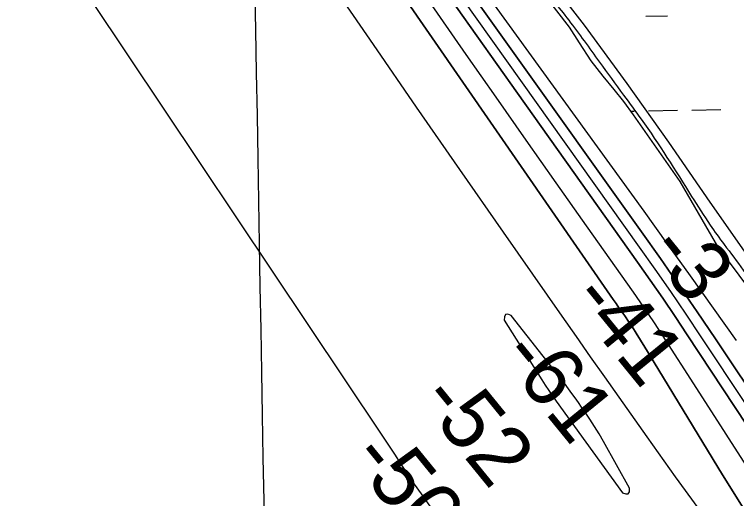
# Model space of a CAD drawing. Extents: x 3892998 to 3931244, y 278583 to 304547.
# Drawn here: x 3912822 to 3913620, y 290539 to 291075 of the extents above; entities that cross this region are included whole.
import ezdxf

# ---------------------------------------------------------------- set-up
doc = ezdxf.new("R2010")
doc.units = 0
for name, color, linetype in [('V-GRID-MAJR', 7, 'Continuous'), ('V-RIVR-EDGE', 7, 'Continuous'), ('V-RIVR-RANG', 7, 'Continuous'), ('V-RRAP-FSHR', 7, 'Continuous'), ('V-TOPO-DPTH', 7, 'Continuous'), ('V-TOPO-MAJR', 7, 'Continuous'), ('V-TOPO-MINR', 7, 'Continuous'), ('V-WETL-SWMP', 7, 'Continuous')]:
    doc.layers.add(name, color=color, linetype=linetype)

msp = doc.modelspace()

# ---------------------------------------------------------------- linework, layer by layer
at = {"layer": 'V-GRID-MAJR'}
for points in [[(3913205.694, 284291.167), (3913100.856, 290347.625), (3912995.9590000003, 296407.553), (3912891.061, 302467.47500000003), (3912891.001, 302470.95)], [(3897162.872, 290075.216), (3902475.546, 290165.246), (3907788.208, 290256.049), (3913100.856, 290347.625), (3918413.491, 290439.973), (3923726.113, 290533.094), (3929038.721, 290626.988)]]:
    msp.add_spline(points, degree=3, dxfattribs=at)
at = {"layer": 'V-RIVR-EDGE'}
msp.add_spline([(3912905.462429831, 291820.09187449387), (3912916.1993131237, 291798.1348694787), (3912921.3932742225, 291786.9827471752), (3912931.4339568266, 291765.0274636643), (3912935.9162236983, 291747.61125666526), (3912940.4122626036, 291735.7646551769), (3912954.9722244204, 291711.36147947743), (3912961.5198530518, 291684.5413986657), (3912964.258175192, 291665.73709404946), (3912967.0128516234, 291653.54669597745), (3912976.0161192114, 291634.37879747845), (3912985.7104229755, 291613.1205754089), (3912986.385104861, 291604.416345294), (3912990.545093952, 291597.4440093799), (3912997.1486714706, 291593.25045095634), (3913007.576188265, 291586.9588221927), (3913014.1746012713, 291580.67666170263), (3913019.3633978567, 291567.43593733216), (3913026.994061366, 291556.2777897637), (3913048.1808410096, 291537.07976494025), (3913061.368198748, 291520.68634017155), (3913079.061924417, 291496.62351804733), (3913103.011127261, 291468.3679982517), (3913127.304126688, 291438.37111598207), (3913184.9441775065, 291379.7473732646), (3913206.1163243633, 291354.63164258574), (3913225.1955653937, 291327.780574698), (3913253.290124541, 291286.6350131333), (3913265.0962706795, 291274.77033585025), (3913279.3373977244, 291262.20343261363), (3913304.672976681, 291231.5077673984), (3913329.3132157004, 291201.16192403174), (3913355.687931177, 291168.3750744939), (3913376.51197769, 291143.26020456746), (3913400.8006733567, 291111.5228205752), (3913434.460534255, 291068.62298525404), (3913468.459887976, 291022.24128573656), (3913495.173235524, 290985.624471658), (3913514.60143765, 290959.12064336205), (3913570.4347088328, 290873.69747788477), (3913590.894300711, 290841.9695621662), (3913606.505449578, 290820.3486069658), (3913627.3217493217, 290792.10083393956), (3913641.190674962, 290769.7879818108), (3913669.62730919, 290726.20485708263), (3913686.621391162, 290700.7513550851), (3913705.714404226, 290679.46989270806), (3913722.034665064, 290663.06872116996), (3913741.1182098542, 290637.958155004), (3913763.668125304, 290606.9212754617), (3913781.0301049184, 290589.47322063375)], degree=3, dxfattribs=at)
at = {"layer": 'V-RRAP-FSHR'}
msp.add_lwpolyline([(3912906.2273111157, 291748.72141911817), (3912937.3302871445, 291675.2780910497), (3912988.1370711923, 291613.8770029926), (3913041.368687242, 291554.15732293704), (3913094.463087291, 291494.31885888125), (3913147.23595134, 291434.1936748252), (3913198.9479513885, 291373.15508276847), (3913250.2749274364, 291311.79495471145), (3913301.436015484, 291250.29351465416), (3913352.4148315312, 291188.64052259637), (3913402.6399835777, 291126.37722653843), (3913451.671151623, 291063.17799447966), (3913498.9103196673, 290998.61479441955), (3913544.746607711, 290933.480202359), (3913590.484591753, 290867.4137702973), (3913636.3208797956, 290801.84705023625)], dxfattribs=at)
at = {"layer": 'V-TOPO-DPTH'}
for points in [[(3912897.1451768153, 291673.0771983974), (3912905.4272677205, 291652.21579509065), (3912915.4203108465, 291631.9170253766), (3913041.9467947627, 291409.9072882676), (3913059.8933273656, 291379.3466368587), (3913078.3588966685, 291349.1123106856), (3913097.603021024, 291319.3674723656), (3913117.366182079, 291289.94895928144), (3913483.676371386, 290759.6812828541), (3913486.861552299, 290755.08465931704), (3913490.055569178, 290750.49420277), (3913493.2628400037, 290745.9129967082), (3913496.478946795, 290741.33795763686), (3913501.5266543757, 290734.17940441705), (3913502.217506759, 290733.1829194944), (3913502.897661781, 290732.1793083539), (3913504.2151823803, 290730.1435812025), (3913507.847480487, 290724.36477111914), (3913510.3003555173, 290720.4432378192), (3913512.741687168, 290716.51456646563), (3913515.165703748, 290712.5751880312), (3913517.578176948, 290708.6286715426), (3913604.584874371, 290565.5897350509), (3913651.4089650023, 290490.7297236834)], [(3913736.7739366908, 290460.95166721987), (3913565.6152656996, 290720.6767830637), (3913552.1224241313, 290740.91804081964), (3913538.4882412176, 290761.0625437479), (3913524.6420462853, 290781.0619144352), (3913510.6545100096, 290800.96453029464), (3913377.8013416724, 290987.8925058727), (3913332.7934826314, 291051.4249503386), (3913287.915268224, 291115.048546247), (3913243.2315207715, 291178.80886931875), (3913198.6774179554, 291242.6603438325), (3913127.6844999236, 291344.73357149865), (3913118.9028194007, 291357.7295626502), (3913110.359043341, 291370.87565585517), (3913102.1721239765, 291384.2469021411), (3913094.223109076, 291397.7682504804), (3913076.2252892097, 291429.3480772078)], [(3913076.2252892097, 291429.3480772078), (3913094.223109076, 291397.7682504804), (3913102.1721239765, 291384.2469021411), (3913110.359043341, 291370.87565585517), (3913118.9028194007, 291357.7295626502), (3913127.6844999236, 291344.73357149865), (3913198.6774179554, 291242.6603438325), (3913243.2315207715, 291178.80886931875), (3913287.915268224, 291115.048546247), (3913332.7934826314, 291051.4249503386), (3913377.8013416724, 290987.8925058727), (3913510.6545100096, 290800.96453029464), (3913524.6420462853, 290781.0619144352), (3913538.4882412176, 290761.0625437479), (3913552.1224241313, 290740.91804081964), (3913565.6152656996, 290720.6767830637), (3913736.7739366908, 290460.95166721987)], [(3913036.6081723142, 291419.2747039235), (3913041.9467947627, 291409.9072882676), (3913059.8933273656, 291379.3466368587), (3913078.3588966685, 291349.1123106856), (3913097.603021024, 291319.3674723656), (3913117.366182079, 291289.94895928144), (3913483.676371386, 290759.6812828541), (3913486.861552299, 290755.08465931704), (3913490.055569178, 290750.49420277), (3913493.2628400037, 290745.9129967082), (3913496.478946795, 290741.33795763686), (3913501.5266543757, 290734.17940441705), (3913502.217506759, 290733.1829194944), (3913502.897661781, 290732.1793083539), (3913504.2151823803, 290730.1435812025), (3913507.847480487, 290724.36477111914), (3913510.3003555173, 290720.4432378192), (3913512.741687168, 290716.51456646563), (3913515.165703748, 290712.5751880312), (3913517.578176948, 290708.6286715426), (3913604.584874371, 290565.5897350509), (3913651.4089650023, 290490.7297236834)], [(3913102.566354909, 291422.9241536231), (3913120.3614544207, 291391.69883888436), (3913123.305762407, 291386.6930337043), (3913126.3396415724, 291381.7438374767), (3913129.507877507, 291376.87955467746), (3913132.7656846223, 291372.07188083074), (3913158.6143120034, 291335.0286831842), (3913174.899976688, 291311.7675169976), (3913191.2339720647, 291288.5404514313), (3913207.6404634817, 291265.36453679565), (3913224.0952855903, 291242.2227227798), (3913515.117934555, 290834.28385512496), (3913535.8222699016, 290804.9764650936), (3913556.3448589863, 290775.54359221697), (3913576.5948286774, 290745.9224950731), (3913596.663052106, 290716.1759150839), (3913931.3713744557, 290215.07261771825)], [(3913637.8285300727, 290565.33774090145), (3913608.70807324, 290610.76501241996), (3913579.484463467, 290656.12640665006), (3913534.7510898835, 290725.30355324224), (3913527.750106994, 290735.98182222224), (3913520.6602326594, 290746.59992313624), (3913513.4370211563, 290757.1277719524), (3913506.1249182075, 290767.595452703), (3913454.0086447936, 290841.20960855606), (3913420.642193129, 290888.48860010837), (3913387.369714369, 290935.83342436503), (3913354.2381949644, 290983.27699767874), (3913321.2006484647, 291030.7864036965), (3913122.5521167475, 291317.35974646)], [(3913637.8285300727, 290565.33774090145), (3913608.70807324, 290610.76501241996), (3913579.484463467, 290656.12640665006), (3913534.7510898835, 290725.30355324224), (3913527.750106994, 290735.98182222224), (3913520.6602326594, 290746.59992313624), (3913513.4370211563, 290757.1277719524), (3913506.1249182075, 290767.595452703), (3913454.0086447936, 290841.20960855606), (3913420.642193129, 290888.48860010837), (3913387.369714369, 290935.83342436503), (3913354.2381949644, 290983.27699767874), (3913321.2006484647, 291030.7864036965), (3913122.5521167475, 291317.35974646)]]:
    msp.add_lwpolyline(points, dxfattribs=at)
at = {"layer": 'V-TOPO-MAJR'}
for points in [[(3912484.064907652, 291701.969517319), (3912531.0426652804, 291634.52324090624), (3912577.9783023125, 291567.04764613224), (3912624.885858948, 291499.552505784), (3912816.6482854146, 291223.4422397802), (3912829.138379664, 291205.35373427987), (3912841.5627439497, 291187.2204542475), (3912853.8885132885, 291169.0200124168), (3912866.1485526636, 291150.7747960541), (3913226.975114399, 290610.63741017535), (3913234.3440935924, 290599.5889253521), (3913241.7022584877, 290588.5332544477), (3913249.0442019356, 290577.4668044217), (3913256.375331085, 290566.3931683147), (3913263.790301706, 290555.3787180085), (3913271.3277941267, 290544.4503112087), (3913279.0490692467, 290533.65096966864), (3913286.892866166, 290522.9376716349), (3913293.4498227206, 290514.13910575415), (3913304.5791366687, 290499.0302373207), (3913315.5952651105, 290483.8402416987), (3913326.4416152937, 290468.5285552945), (3913337.1747799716, 290453.1357417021), (3913674.6564096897, 289963.352789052)], [(3913584.4846489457, 290519.3721680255), (3913552.73962614, 290563.3977001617), (3913521.237944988, 290607.6002385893), (3913490.119972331, 290651.6507728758), (3913474.377372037, 290673.973155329), (3913458.658183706, 290696.31198461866), (3913442.974113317, 290718.6754841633), (3913427.3134548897, 290741.0554305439), (3913362.257074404, 290834.1802491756), (3913314.203634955, 290903.21627821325), (3913266.3073248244, 290972.360755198), (3913218.6467086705, 291041.66790410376), (3913171.143221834, 291111.083500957)]]:
    msp.add_lwpolyline(points, dxfattribs=at)
at = {"layer": 'V-TOPO-MINR'}
for points in [[(3913651.4089650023, 290490.7297236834), (3913604.584874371, 290565.5897350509), (3913517.578176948, 290708.6286715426), (3913515.165703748, 290712.5751880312), (3913512.741687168, 290716.51456646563), (3913510.3003555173, 290720.4432378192), (3913507.847480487, 290724.36477111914), (3913504.2151823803, 290730.1435812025), (3913502.897661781, 290732.1793083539), (3913502.217506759, 290733.1829194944), (3913501.5266543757, 290734.17940441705), (3913496.478946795, 290741.33795763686), (3913493.2628400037, 290745.9129967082), (3913490.055569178, 290750.49420277), (3913486.861552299, 290755.08465931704), (3913483.676371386, 290759.6812828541), (3913117.366182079, 291289.94895928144), (3913097.603021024, 291319.3674723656), (3913078.3588966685, 291349.1123106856), (3913059.8933273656, 291379.3466368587), (3913041.9467947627, 291409.9072882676), (3912915.4203108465, 291631.9170253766), (3912905.4272677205, 291652.21579509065), (3912897.1451768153, 291673.0771983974)], [(3913620.1941250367, 290714.21305653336), (3913594.736994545, 290750.0982914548), (3913569.19605935, 290785.9235571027), (3913543.5294171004, 290821.6588688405), (3913517.7789701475, 290857.33421130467), (3913148.9031195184, 291366.4973075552), (3913146.437676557, 291369.91851225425), (3913143.9837869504, 291373.34793985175), (3913141.547227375, 291376.78970179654), (3913139.122221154, 291380.23968664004), (3913135.287172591, 291385.7250522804), (3913134.3235224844, 291387.1734852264), (3913133.8688546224, 291387.9148784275), (3913133.4277653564, 291388.66485999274), (3913130.4900239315, 291393.82214557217), (3913129.43825995, 291396.49498069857), (3913129.2879027, 291399.34639505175), (3913136.7595498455, 291458.03431484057)], [(3913736.7739366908, 290460.95166721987), (3913565.6152656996, 290720.6767830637), (3913552.1224241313, 290740.91804081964), (3913538.4882412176, 290761.0625437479), (3913524.6420462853, 290781.0619144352), (3913510.6545100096, 290800.96453029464), (3913377.8013416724, 290987.8925058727), (3913332.7934826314, 291051.4249503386), (3913287.915268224, 291115.048546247), (3913243.2315207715, 291178.80886931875), (3913198.6774179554, 291242.6603438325), (3913127.6844999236, 291344.73357149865), (3913118.9028194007, 291357.7295626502), (3913110.359043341, 291370.87565585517), (3913102.1721239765, 291384.2469021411), (3913094.223109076, 291397.7682504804), (3913076.2252892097, 291429.3480772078)], [(3913831.8149811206, 290340.75298341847), (3913581.120458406, 290718.41441440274), (3913564.348268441, 290743.4135949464), (3913547.4135816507, 290768.3010322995), (3913530.235149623, 290793.020854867), (3913512.8942207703, 290817.6289342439), (3913300.39997266, 291116.0492439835), (3913269.7595659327, 291159.22065063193), (3913239.2082944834, 291202.4548381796), (3913208.790725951, 291245.7831970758), (3913178.462292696, 291289.17433687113), (3913130.2312612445, 291358.4063613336), (3913124.2086764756, 291367.3065502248), (3913118.3504509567, 291376.31052812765), (3913112.738764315, 291385.47018954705), (3913107.2914369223, 291394.73363997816), (3913088.9949535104, 291426.83734434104)], [(3913931.3713744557, 290215.07261771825), (3913596.663052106, 290716.1759150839), (3913576.5948286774, 290745.9224950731), (3913556.3448589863, 290775.54359221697), (3913535.8222699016, 290804.9764650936), (3913515.117934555, 290834.28385512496), (3913224.0952855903, 291242.2227227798), (3913207.6404634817, 291265.36453679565), (3913191.2339720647, 291288.5404514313), (3913174.899976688, 291311.7675169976), (3913158.6143120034, 291335.0286831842), (3913132.7656846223, 291372.07188083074), (3913129.507877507, 291376.87955467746), (3913126.3396415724, 291381.7438374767), (3913123.305762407, 291386.6930337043), (3913120.3614544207, 291391.69883888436), (3913102.566354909, 291422.9241536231)], [(3913637.8285300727, 290565.33774090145), (3913608.70807324, 290610.76501241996), (3913579.484463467, 290656.12640665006), (3913534.7510898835, 290725.30355324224), (3913527.750106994, 290735.98182222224), (3913520.6602326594, 290746.59992313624), (3913513.4370211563, 290757.1277719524), (3913506.1249182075, 290767.595452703), (3913454.0086447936, 290841.20960855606), (3913420.642193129, 290888.48860010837), (3913387.369714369, 290935.83342436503), (3913354.2381949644, 290983.27699767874), (3913321.2006484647, 291030.7864036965), (3913122.5521167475, 291317.35974646)], [(3913441.624845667, 290650.65862612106), (3913438.00617635, 290655.6862305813), (3913434.3619471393, 290660.6955851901), (3913429.8403065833, 290666.86160384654), (3913427.003259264, 290670.6626964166), (3913424.102452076, 290674.41535678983), (3913370.928002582, 290742.01802727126), (3913367.187484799, 290743.2215388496), (3913364.4812388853, 290742.95904272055), (3913363.3264007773, 290740.4975350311), (3913363.2058345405, 290736.5700196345), (3913404.661500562, 290670.7865892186), (3913408.521980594, 290664.79095880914), (3913412.4591678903, 290658.84722228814), (3913416.5114160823, 290652.9813265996), (3913420.640371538, 290647.1673247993), (3913494.1268024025, 290545.7977067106), (3913497.6977241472, 290544.47843692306), (3913500.334821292, 290544.6203269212), (3913501.5711815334, 290546.9539565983), (3913501.8737171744, 290550.7487460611), (3913472.8951830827, 290602.54567135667), (3913468.101936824, 290610.8270693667), (3913463.1508526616, 290619.00978913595), (3913457.963011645, 290627.04449154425), (3913452.6173327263, 290634.98051571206), (3913448.75994472, 290640.53041779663), (3913445.205175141, 290645.60364688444), (3913441.624845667, 290650.65862612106)]]:
    msp.add_lwpolyline(points, dxfattribs=at)
at = {"layer": 'V-WETL-SWMP'}
for p, q in [((3913435.2559981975, 291060.8669986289), (3913403.4859981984, 291102.0899986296)), ((3913519.730366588, 291072.98267594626), (3913543.7267716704, 291073.39805755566)), ((3913446.2679982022, 291043.6259986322), (3913435.2559981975, 291060.8669986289)), ((3913459.2969982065, 291023.69699863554), (3913446.2679982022, 291043.6259986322)), ((3913472.6089982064, 291006.5709986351), (3913459.296998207, 291023.69699863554)), ((3913484.9069982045, 290991.7389986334), (3913472.6089982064, 291006.5709986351)), ((3913495.3939982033, 290978.4979986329), (3913484.9069982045, 290991.7389986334)), ((3913506.2889982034, 290963.95799863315), (3913495.3939982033, 290978.4979986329)), ((3913503.2292828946, 290968.04136353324), (3913506.699654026, 290968.10143621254)), ((3913557.7689982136, 290890.1399986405), (3913506.2889982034, 290963.95799863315)), ((3913522.697257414, 290968.3783572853), (3913554.6924641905, 290968.9321994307)), ((3913570.6900675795, 290969.20912050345), (3913602.685274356, 290969.76296264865)), ((3913586.0859982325, 290841.09099865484), (3913557.768998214, 290890.1399986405)), ((3913599.3339982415, 290818.06099866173), (3913586.0859982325, 290841.09099865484)), ((3913634.7439982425, 290770.7569986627), (3913599.3339982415, 290818.06099866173))]:
    msp.add_line(p, q, dxfattribs=at)

# ---------------------------------------------------------------- texts
at = {"layer": 'V-RIVR-RANG'}
for s, height, rotation, p in [('-3', 66.9999999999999, 308.87832571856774, (3913519.703238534, 290813.4672054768)), ('-41', 67, 309.16555555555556, (3913434.4198283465, 290759.41021056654)), ('-61', 67, 309.16555555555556, (3913356.7308283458, 290696.4452105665)), ('-52', 67, 309.16555555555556, (3913267.2146917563, 290648.0017527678)), ('-50', 67, 309.16555555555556, (3913190.691846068, 290583.6061500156))]:
    msp.add_text(s, height=height, rotation=rotation, dxfattribs=at).set_placement(p)

doc.saveas('drawing.dxf')
